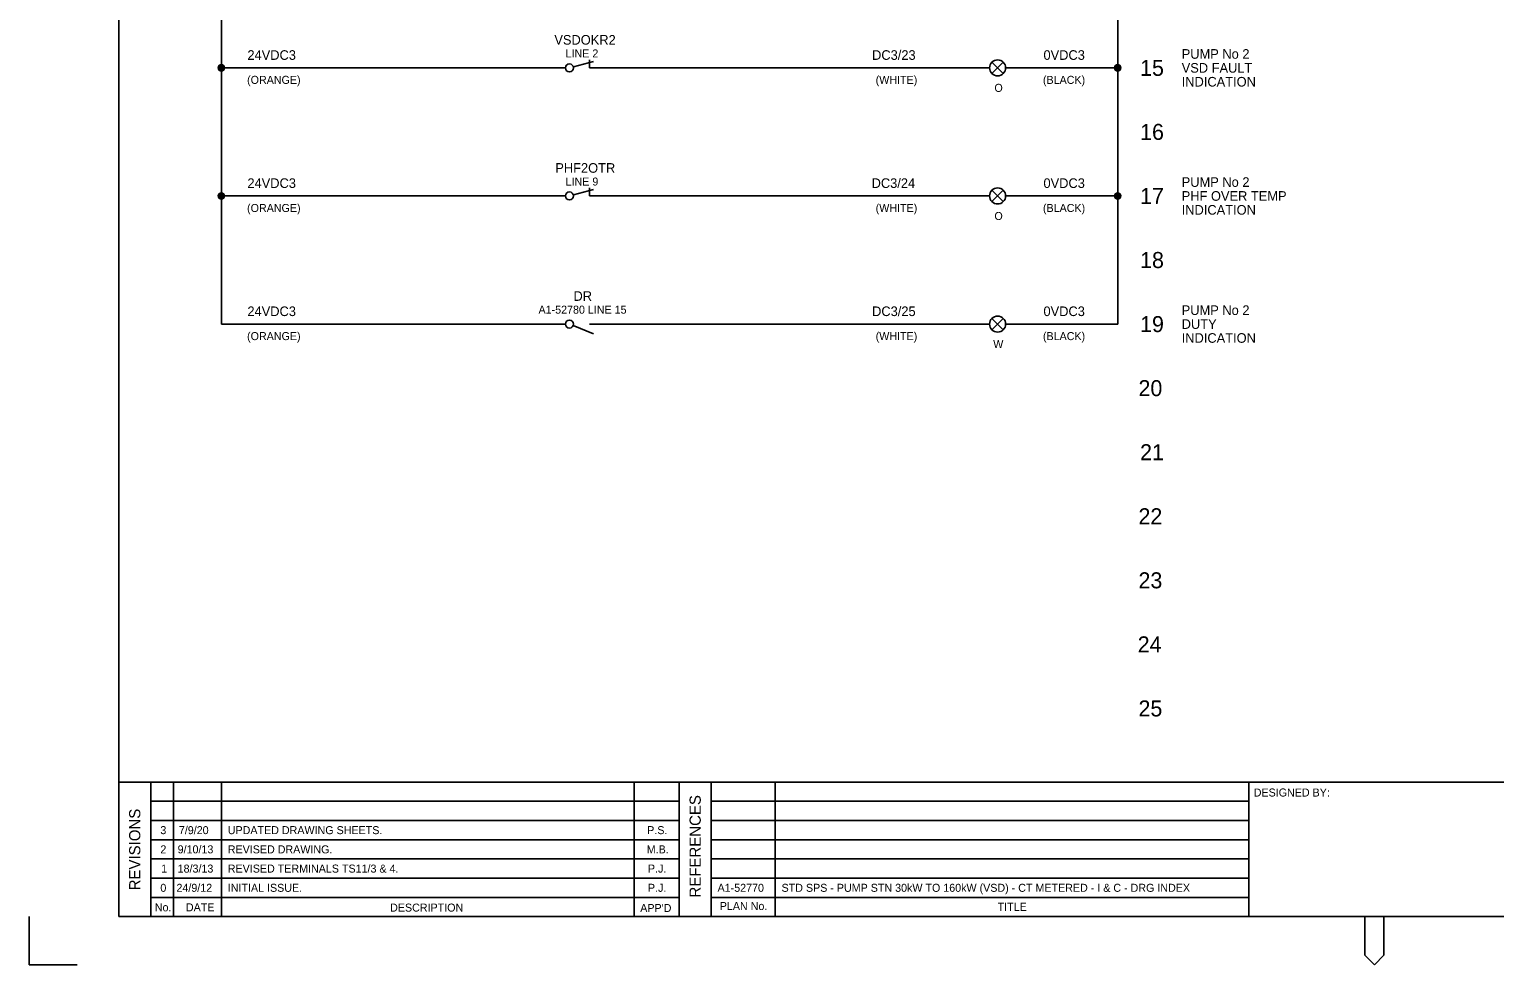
# Model space of a CAD drawing. Extents: x 0 to 841, y 0 to 594.
# Drawn here: x 0 to 457.8, y 0 to 292 of the extents above; entities that cross this region are included whole.
import ezdxf

# ---------------------------------------------------------------- set-up
doc = ezdxf.new("R2010")
doc.units = 0
for name, color, linetype in [('A1BORDER', 7, 'Continuous'), ('Level 1', 7, 'Continuous'), ('Level 10', 7, 'Continuous'), ('Level 5', 7, 'Continuous'), ('Level 6', 7, 'Continuous')]:
    doc.layers.add(name, color=color, linetype=linetype)

msp = doc.modelspace()

# ---------------------------------------------------------------- linework, layer by layer
at = {"layer": 'A1BORDER'}
for p, q in [((28, 581), (28, 15)), ((28, 57), (829, 57)), ((38, 15), (38, 57)), ((45, 15), (45, 57)), ((60, 15), (60, 57)), ((189, 15), (189, 57)), ((203, 15), (203, 57)), ((213, 15), (213, 57)), ((233, 15), (233, 57)), ((381, 15), (381, 57)), ((203, 51), (38, 51)), ((213, 51), (381, 51)), ((203, 45), (38, 45)), ((213, 45), (381, 45)), ((203, 39), (38, 39)), ((213, 39), (381, 39)), ((203, 33), (38, 33)), ((213, 33), (381, 33)), ((38, 27), (203, 27)), ((213, 27), (381, 27)), ((203, 21), (38, 21)), ((213, 21), (381, 21)), ((0, 0), (0, 15)), ((829, 15), (28, 15)), ((417.19, 15), (417.19, 3)), ((423.19, 15), (423.19, 3)), ((0, 0), (15, 0)), ((417.19, 3), (420.19, 0)), ((423.19, 3), (420.19, 0))]:
    msp.add_line(p, q, dxfattribs=at)
at = {"layer": 'Level 1'}
for p, q in [((60, 200), (60, 560)), ((340, 200), (340, 560)), ((60, 280), (167.5, 280)), ((175, 280), (177.5, 280)), ((305, 280), (340, 280)), ((60, 240), (167.5, 240)), ((175, 240), (177.5, 240)), ((305, 240), (340, 240)), ((60, 200), (167.5, 200)), ((167.5, 200), (167.5, 200)), ((175, 200), (177.5, 200)), ((177.5, 200), (177.5, 200)), ((305, 200), (340, 200))]:
    msp.add_line(p, q, dxfattribs=at)
at = {"layer": 'Level 10'}
for p, q in [((59.1, 280.44), (59.1, 279.56)), ((59.4, 280.8), (59.4, 279.2)), ((59.7, 280.95), (59.7, 279.05)), ((60, 281), (60, 279.01)), ((60.3, 280.95), (60.3, 279.05)), ((60.6, 280.8), (60.6, 279.2)), ((60.9, 280.44), (60.9, 279.56)), ((61, 280), (61, 280)), ((169.96, 280.32), (176.25, 282)), ((175, 282.5), (175, 280)), ((304.27, 281.77), (300.73, 278.23)), ((300.73, 281.77), (304.27, 278.23)), ((339.1, 280.44), (339.1, 279.56)), ((339.4, 280.8), (339.4, 279.2)), ((339.7, 280.95), (339.7, 279.05)), ((340, 281), (340, 279.01)), ((340.3, 280.95), (340.3, 279.05)), ((340.6, 280.8), (340.6, 279.2)), ((340.9, 280.44), (340.9, 279.56)), ((341, 280), (341, 280)), ((59.1, 240.44), (59.1, 239.56)), ((59.4, 240.8), (59.4, 239.2)), ((59.7, 240.95), (59.7, 239.05)), ((60, 241), (60, 239.01)), ((60.3, 240.95), (60.3, 239.05)), ((60.6, 240.8), (60.6, 239.2)), ((60.9, 240.44), (60.9, 239.56)), ((61, 240), (61, 240)), ((169.96, 240.32), (176.25, 242)), ((175, 242.5), (175, 240)), ((304.27, 241.77), (300.73, 238.23)), ((300.73, 241.77), (304.27, 238.23)), ((339.1, 240.44), (339.1, 239.56)), ((339.4, 240.8), (339.4, 239.2)), ((339.7, 240.95), (339.7, 239.05)), ((340, 241), (340, 239.01)), ((340.3, 240.95), (340.3, 239.05)), ((340.6, 240.8), (340.6, 239.2)), ((340.9, 240.44), (340.9, 239.56)), ((341, 240), (341, 240)), ((304.27, 201.77), (300.73, 198.23)), ((300.73, 201.77), (304.27, 198.23)), ((169.91, 199.54), (176.25, 197))]:
    msp.add_line(p, q, dxfattribs=at)
for centre, radius in [((60, 280), 1), ((168.75, 280), 1.25), ((302.5, 280), 2.5), ((340, 280), 1), ((60, 240), 1), ((168.75, 240), 1.25), ((302.5, 240), 2.5), ((340, 240), 1), ((302.5, 200), 2.5), ((168.75, 200), 1.25)]:
    msp.add_circle(centre, radius, dxfattribs=at)
at = {"layer": 'Level 6'}
for p, q in [((177.5, 280), (300, 280)), ((177.5, 240), (300, 240)), ((177.5, 200), (300, 200))]:
    msp.add_line(p, q, dxfattribs=at)

# ---------------------------------------------------------------- texts
at = {"layer": 'A1BORDER'}
for s, p in [('DESIGNED BY:', (382.5, 52.5)), ('No.', (39.21, 16.65)), ('DATE', (48.92, 16.65)), ('DESCRIPTION', (112.71, 16.57)), ("APP'D", (190.85, 16.44)), ('PLAN No.', (215.69, 17.06)), ('TITLE', (302.5, 16.81))]:
    msp.add_text(s, height=2.5, dxfattribs=at).set_placement(p)
for s, p in [('REFERENCES', (209.76, 20.96)), ('REVISIONS', (34.68, 23.2))]:
    msp.add_text(s, height=3.5, rotation=90, dxfattribs=at).set_placement(p)
at = {"layer": 'Level 1'}
for s, height, p in [('15', 5, (347.01, 277.5)), ('16', 5, (347.01, 257.5)), ('17', 5, (347.01, 237.5)), ('18', 5, (347.01, 217.5)), ('19', 5, (347.01, 197.5)), ('20', 5, (346.51, 177.5)), ('21', 5, (347.01, 157.5)), ('22', 5, (346.51, 137.5)), ('23', 5, (346.51, 117.5)), ('24', 5, (346.26, 97.5)), ('25', 5, (346.51, 77.5)), ('3', 2.5, (40.94, 40.75)), ('7/9/20', 2.5, (46.72, 40.75)), ('UPDATED DRAWING SHEETS.', 2.5, (62, 40.75)), ('P.S.', 2.5, (193.02, 40.75)), ('2', 2.5, (40.94, 34.75)), ('9/10/13', 2.5, (46.34, 34.75)), ('REVISED DRAWING.', 2.5, (62, 34.75)), ('M.B.', 2.5, (192.89, 34.75)), ('1', 2.5, (41.19, 28.75)), ('18/3/13', 2.5, (46.34, 28.75)), ('REVISED TERMINALS TS11/3 & 4.', 2.5, (62, 28.75)), ('P.J.', 2.5, (193.26, 28.75)), ('0', 2.5, (40.94, 22.75)), ('24/9/12', 2.5, (45.97, 22.75)), ('INITIAL ISSUE.', 2.5, (62, 22.75)), ('P.J.', 2.5, (193.26, 22.75)), ('A1-52770', 2.5, (215, 22.75)), ('STD SPS - PUMP STN 30kW TO 160kW (VSD) - CT METERED - I & C - DRG INDEX', 2.5, (235, 22.75))]:
    msp.add_text(s, height=height, dxfattribs=at).set_placement(p)
at = {"layer": 'Level 5'}
for s, height, p in [('VSDOKR2', 3, (164.02, 287.25)), ('24VDC3', 3, (68.13, 282.5)), ('LINE 2', 2.5, (167.53, 283.25)), ('DC3/23', 3, (263.28, 282.5)), ('0VDC3', 3, (316.82, 282.5)), ('PUMP No 2', 3, (360, 282.84)), ('VSD FAULT', 3, (360, 278.5)), ('(ORANGE)', 2.5, (68.03, 275)), ('(WHITE)', 2.5, (264.4, 275)), ('O', 2.5, (301.5, 272.5)), ('(BLACK)', 2.5, (316.65, 275)), ('INDICATION', 3, (360, 274.16)), ('PHF2OTR', 3, (164.32, 247.25)), ('24VDC3', 3, (68.13, 242.5)), ('LINE 9', 2.5, (167.53, 243.25)), ('DC3/24', 3, (263.13, 242.5)), ('0VDC3', 3, (316.82, 242.5)), ('PUMP No 2', 3, (360, 242.84)), ('PHF OVER TEMP', 3, (360, 238.5)), ('(ORANGE)', 2.5, (68.03, 235)), ('(WHITE)', 2.5, (264.4, 235)), ('O', 2.5, (301.5, 232.5)), ('(BLACK)', 2.5, (316.65, 235)), ('INDICATION', 3, (360, 234.16)), ('DR', 3, (170, 207.25)), ('24VDC3', 3, (68.13, 202.5)), ('A1-52780 LINE 15', 2.5, (159.07, 203.25)), ('DC3/25', 3, (263.28, 202.5)), ('0VDC3', 3, (316.82, 202.5)), ('PUMP No 2', 3, (360, 202.84)), ('DUTY', 3, (360, 198.5)), ('(ORANGE)', 2.5, (68.03, 195)), ('(WHITE)', 2.5, (264.4, 195)), ('(BLACK)', 2.5, (316.65, 195)), ('INDICATION', 3, (360, 194.16)), ('W', 2.5, (301.13, 192.5))]:
    msp.add_text(s, height=height, dxfattribs=at).set_placement(p)

doc.saveas('drawing.dxf')
